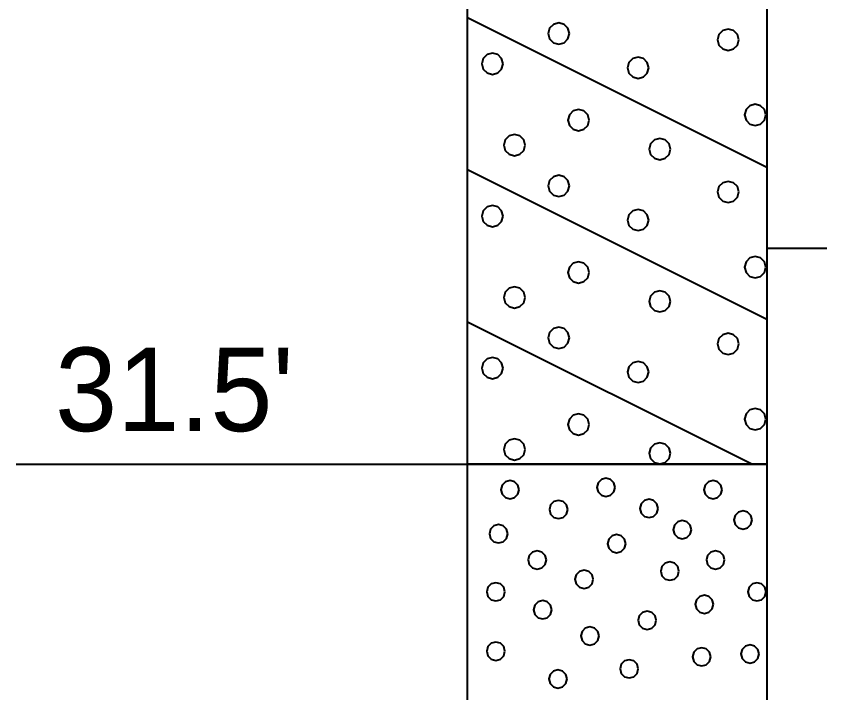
# Model space of a CAD drawing. Extents: x -582 to 653, y -817 to -3.
# Drawn here: x -545.44 to -538.67, y -213.72 to -208.07 of the extents above; entities that cross this region are included whole.
import ezdxf

# ---------------------------------------------------------------- set-up
doc = ezdxf.new("R2010")
doc.units = 0
doc.header["$LTSCALE"] = 0.4
doc.layers.add('27', color=7, linetype='Continuous', lineweight=40)

msp = doc.modelspace()

# ---------------------------------------------------------------- linework, layer by layer
at = {"layer": '27'}
for p, q in [((-541.6718, -208.078), (-539.1718, -209.328)), ((-541.6718, -209.348), (-539.1718, -210.598)), ((-538.6718, -210.008), (-539.1718, -210.008)), ((-541.6718, -210.618), (-539.2918, -211.808)), ((-545.4392, -211.808), (-541.6718, -211.808))]:
    msp.add_line(p, q, dxfattribs=at)
for points in [[(-541.6718, -206.808), (-539.1718, -206.808), (-539.1718, -211.808), (-541.6718, -211.808)], [(-540.8212, -208.2132), (-540.8332, -208.1687), (-540.8657, -208.1362), (-540.9101, -208.1243), (-540.9546, -208.1362), (-540.9871, -208.1687), (-540.999, -208.2132), (-540.9871, -208.2576), (-540.9546, -208.2902), (-540.9101, -208.3021), (-540.8657, -208.2902), (-540.8332, -208.2576)], [(-539.4063, -208.264), (-539.4182, -208.2196), (-539.4508, -208.187), (-539.4952, -208.1751), (-539.5397, -208.187), (-539.5722, -208.2196), (-539.5841, -208.264), (-539.5722, -208.3085), (-539.5397, -208.341), (-539.4952, -208.3529), (-539.4508, -208.341), (-539.4182, -208.3085)], [(-541.3742, -208.4649), (-541.3862, -208.4204), (-541.4187, -208.3879), (-541.4631, -208.376), (-541.5076, -208.3879), (-541.5401, -208.4204), (-541.552, -208.4649), (-541.5401, -208.5093), (-541.5076, -208.5419), (-541.4631, -208.5538), (-541.4187, -208.5419), (-541.3862, -208.5093)], [(-540.1589, -208.4979), (-540.1708, -208.4535), (-540.2034, -208.421), (-540.2478, -208.409), (-540.2923, -208.421), (-540.3248, -208.4535), (-540.3367, -208.4979), (-540.3248, -208.5424), (-540.2923, -208.5749), (-540.2478, -208.5868), (-540.2034, -208.5749), (-540.1708, -208.5424)], [(-539.18, -208.892), (-539.1919, -208.8476), (-539.2245, -208.815), (-539.2689, -208.8031), (-539.3134, -208.815), (-539.3459, -208.8476), (-539.3578, -208.892), (-539.3459, -208.9365), (-539.3134, -208.969), (-539.2689, -208.9809), (-539.2245, -208.969), (-539.1919, -208.9365)], [(-540.6547, -208.9353), (-540.6666, -208.8908), (-540.6992, -208.8583), (-540.7436, -208.8464), (-540.7881, -208.8583), (-540.8206, -208.8908), (-540.8325, -208.9353), (-540.8206, -208.9797), (-540.7881, -209.0122), (-540.7436, -209.0242), (-540.6992, -209.0122), (-540.6666, -208.9797)], [(-541.1899, -209.1437), (-541.2018, -209.0993), (-541.2344, -209.0668), (-541.2788, -209.0548), (-541.3233, -209.0668), (-541.3558, -209.0993), (-541.3677, -209.1437), (-541.3558, -209.1882), (-541.3233, -209.2207), (-541.2788, -209.2326), (-541.2344, -209.2207), (-541.2018, -209.1882)], [(-539.9771, -209.1768), (-539.989, -209.1324), (-540.0216, -209.0998), (-540.066, -209.0879), (-540.1105, -209.0998), (-540.143, -209.1324), (-540.1549, -209.1768), (-540.143, -209.2213), (-540.1105, -209.2538), (-540.066, -209.2657), (-540.0216, -209.2538), (-539.989, -209.2213)], [(-540.8212, -209.4844), (-540.8331, -209.4399), (-540.8656, -209.4074), (-540.9101, -209.3955), (-540.9545, -209.4074), (-540.9871, -209.4399), (-540.999, -209.4844), (-540.9871, -209.5288), (-540.9545, -209.5614), (-540.9101, -209.5733), (-540.8656, -209.5614), (-540.8331, -209.5288)], [(-539.4063, -209.5353), (-539.4182, -209.4908), (-539.4508, -209.4583), (-539.4952, -209.4464), (-539.5397, -209.4583), (-539.5722, -209.4908), (-539.5841, -209.5353), (-539.5722, -209.5797), (-539.5397, -209.6123), (-539.4952, -209.6242), (-539.4508, -209.6123), (-539.4182, -209.5797)], [(-541.3742, -209.7362), (-541.3862, -209.6917), (-541.4187, -209.6592), (-541.4631, -209.6473), (-541.5076, -209.6592), (-541.5401, -209.6917), (-541.552, -209.7362), (-541.5401, -209.7806), (-541.5076, -209.8132), (-541.4631, -209.8251), (-541.4187, -209.8132), (-541.3862, -209.7806)], [(-540.1589, -209.7692), (-540.1708, -209.7248), (-540.2034, -209.6922), (-540.2478, -209.6803), (-540.2923, -209.6922), (-540.3248, -209.7248), (-540.3367, -209.7692), (-540.3248, -209.8137), (-540.2923, -209.8462), (-540.2478, -209.8581), (-540.2034, -209.8462), (-540.1708, -209.8137)], [(-540.6547, -210.2065), (-540.6666, -210.1621), (-540.6992, -210.1295), (-540.7436, -210.1176), (-540.7881, -210.1295), (-540.8206, -210.1621), (-540.8325, -210.2065), (-540.8206, -210.251), (-540.7881, -210.2835), (-540.7436, -210.2954), (-540.6992, -210.2835), (-540.6666, -210.251)], [(-539.18, -210.1633), (-539.1919, -210.1189), (-539.2245, -210.0863), (-539.2689, -210.0744), (-539.3134, -210.0863), (-539.3459, -210.1189), (-539.3578, -210.1633), (-539.3459, -210.2078), (-539.3134, -210.2403), (-539.2689, -210.2522), (-539.2245, -210.2403), (-539.1919, -210.2078)], [(-541.1899, -210.415), (-541.2018, -210.3706), (-541.2344, -210.338), (-541.2788, -210.3261), (-541.3233, -210.338), (-541.3558, -210.3706), (-541.3677, -210.415), (-541.3558, -210.4595), (-541.3233, -210.492), (-541.2788, -210.5039), (-541.2344, -210.492), (-541.2018, -210.4595)], [(-539.9771, -210.4481), (-539.989, -210.4036), (-540.0216, -210.3711), (-540.066, -210.3592), (-540.1105, -210.3711), (-540.143, -210.4036), (-540.1549, -210.4481), (-540.143, -210.4925), (-540.1105, -210.5251), (-540.066, -210.537), (-540.0216, -210.5251), (-539.989, -210.4925)], [(-540.8212, -210.7532), (-540.8332, -210.7087), (-540.8657, -210.6762), (-540.9101, -210.6643), (-540.9546, -210.6762), (-540.9871, -210.7087), (-540.999, -210.7532), (-540.9871, -210.7976), (-540.9546, -210.8302), (-540.9101, -210.8421), (-540.8657, -210.8302), (-540.8332, -210.7976)], [(-539.4063, -210.804), (-539.4182, -210.7596), (-539.4508, -210.727), (-539.4952, -210.7151), (-539.5397, -210.727), (-539.5722, -210.7596), (-539.5841, -210.804), (-539.5722, -210.8485), (-539.5397, -210.881), (-539.4952, -210.8929), (-539.4508, -210.881), (-539.4182, -210.8485)], [(-541.3742, -211.0049), (-541.3862, -210.9604), (-541.4187, -210.9279), (-541.4631, -210.916), (-541.5076, -210.9279), (-541.5401, -210.9604), (-541.552, -211.0049), (-541.5401, -211.0493), (-541.5076, -211.0819), (-541.4631, -211.0938), (-541.4187, -211.0819), (-541.3862, -211.0493)], [(-540.1589, -211.0379), (-540.1708, -210.9935), (-540.2034, -210.961), (-540.2478, -210.949), (-540.2923, -210.961), (-540.3248, -210.9935), (-540.3367, -211.0379), (-540.3248, -211.0824), (-540.2923, -211.1149), (-540.2478, -211.1268), (-540.2034, -211.1149), (-540.1708, -211.0824)], [(-539.18, -211.432), (-539.1919, -211.3876), (-539.2245, -211.355), (-539.2689, -211.3431), (-539.3134, -211.355), (-539.3459, -211.3876), (-539.3578, -211.432), (-539.3459, -211.4765), (-539.3134, -211.509), (-539.2689, -211.5209), (-539.2245, -211.509), (-539.1919, -211.4765)], [(-540.6547, -211.4753), (-540.6666, -211.4308), (-540.6992, -211.3983), (-540.7436, -211.3864), (-540.7881, -211.3983), (-540.8206, -211.4308), (-540.8325, -211.4753), (-540.8206, -211.5197), (-540.7881, -211.5522), (-540.7436, -211.5642), (-540.6992, -211.5522), (-540.6666, -211.5197)], [(-541.1899, -211.6837), (-541.2018, -211.6393), (-541.2344, -211.6068), (-541.2788, -211.5948), (-541.3233, -211.6068), (-541.3558, -211.6393), (-541.3677, -211.6837), (-541.3558, -211.7282), (-541.3233, -211.7607), (-541.2788, -211.7726), (-541.2344, -211.7607), (-541.2018, -211.7282)], [(-539.9771, -211.7168), (-539.989, -211.6724), (-540.0216, -211.6398), (-540.066, -211.6279), (-540.1105, -211.6398), (-540.143, -211.6724), (-540.1549, -211.7168), (-540.143, -211.7613), (-540.1105, -211.7938), (-540.066, -211.8057), (-540.0216, -211.7938), (-539.989, -211.7613)], [(-541.6718, -211.808), (-539.1718, -211.808), (-539.1718, -216.308), (-541.6718, -216.308)], [(-541.2399, -212.0207), (-541.2502, -211.9826), (-541.278, -211.9547), (-541.3161, -211.9445), (-541.3542, -211.9547), (-541.3821, -211.9826), (-541.3923, -212.0207), (-541.3821, -212.0588), (-541.3542, -212.0867), (-541.3161, -212.0969), (-541.278, -212.0867), (-541.2502, -212.0588)], [(-540.439, -212.0011), (-540.4492, -211.963), (-540.4771, -211.9351), (-540.5152, -211.9249), (-540.5533, -211.9351), (-540.5812, -211.963), (-540.5914, -212.0011), (-540.5812, -212.0392), (-540.5533, -212.0671), (-540.5152, -212.0773), (-540.4771, -212.0671), (-540.4492, -212.0392)], [(-539.5453, -212.0207), (-539.5555, -211.9826), (-539.5834, -211.9548), (-539.6215, -211.9445), (-539.6596, -211.9548), (-539.6875, -211.9826), (-539.6977, -212.0207), (-539.6875, -212.0588), (-539.6596, -212.0867), (-539.6215, -212.0969), (-539.5834, -212.0867), (-539.5555, -212.0588)], [(-540.835, -212.186), (-540.8452, -212.1479), (-540.8731, -212.12), (-540.9112, -212.1098), (-540.9493, -212.12), (-540.9772, -212.1479), (-540.9874, -212.186), (-540.9772, -212.2241), (-540.9493, -212.2519), (-540.9112, -212.2622), (-540.8731, -212.2519), (-540.8452, -212.2241)], [(-540.0799, -212.177), (-540.0901, -212.1389), (-540.118, -212.111), (-540.1561, -212.1008), (-540.1942, -212.111), (-540.2221, -212.1389), (-540.2323, -212.177), (-540.2221, -212.2151), (-540.1942, -212.243), (-540.1561, -212.2532), (-540.118, -212.243), (-540.0901, -212.2151)], [(-539.2945, -212.2728), (-539.3047, -212.2347), (-539.3326, -212.2069), (-539.3707, -212.1966), (-539.4088, -212.2069), (-539.4366, -212.2347), (-539.4469, -212.2728), (-539.4366, -212.3109), (-539.4088, -212.3388), (-539.3707, -212.349), (-539.3326, -212.3388), (-539.3047, -212.3109)], [(-539.8017, -212.3542), (-539.8119, -212.3161), (-539.8398, -212.2882), (-539.8779, -212.278), (-539.916, -212.2882), (-539.9439, -212.3161), (-539.9541, -212.3542), (-539.9439, -212.3923), (-539.916, -212.4202), (-539.8779, -212.4304), (-539.8398, -212.4202), (-539.8119, -212.3923)], [(-541.3361, -212.3885), (-541.3463, -212.3504), (-541.3742, -212.3225), (-541.4123, -212.3123), (-541.4504, -212.3225), (-541.4783, -212.3504), (-541.4885, -212.3885), (-541.4783, -212.4266), (-541.4504, -212.4545), (-541.4123, -212.4647), (-541.3742, -212.4545), (-541.3463, -212.4266)], [(-540.35, -212.4717), (-540.3602, -212.4336), (-540.3881, -212.4057), (-540.4262, -212.3955), (-540.4643, -212.4057), (-540.4922, -212.4336), (-540.5024, -212.4717), (-540.4922, -212.5098), (-540.4643, -212.5377), (-540.4262, -212.5479), (-540.3881, -212.5377), (-540.3602, -212.5098)], [(-541.0132, -212.6072), (-541.0234, -212.5691), (-541.0513, -212.5412), (-541.0894, -212.531), (-541.1275, -212.5412), (-541.1554, -212.5691), (-541.1656, -212.6072), (-541.1554, -212.6453), (-541.1275, -212.6732), (-541.0894, -212.6834), (-541.0513, -212.6732), (-541.0234, -212.6453)], [(-539.5246, -212.6072), (-539.5348, -212.5691), (-539.5627, -212.5412), (-539.6008, -212.531), (-539.6389, -212.5412), (-539.6667, -212.5691), (-539.677, -212.6072), (-539.6667, -212.6453), (-539.6389, -212.6732), (-539.6008, -212.6834), (-539.5627, -212.6732), (-539.5348, -212.6453)], [(-539.9059, -212.7), (-539.9161, -212.6619), (-539.944, -212.634), (-539.9821, -212.6238), (-540.0202, -212.634), (-540.0481, -212.6619), (-540.0583, -212.7), (-540.0481, -212.7381), (-540.0202, -212.766), (-539.9821, -212.7762), (-539.944, -212.766), (-539.9161, -212.7381)], [(-540.6217, -212.7686), (-540.6319, -212.7305), (-540.6598, -212.7027), (-540.6979, -212.6924), (-540.736, -212.7027), (-540.7638, -212.7305), (-540.7741, -212.7686), (-540.7638, -212.8067), (-540.736, -212.8346), (-540.6979, -212.8448), (-540.6598, -212.8346), (-540.6319, -212.8067)], [(-541.359, -212.8729), (-541.3692, -212.8348), (-541.3971, -212.8069), (-541.4352, -212.7967), (-541.4733, -212.8069), (-541.5012, -212.8348), (-541.5114, -212.8729), (-541.5012, -212.911), (-541.4733, -212.9389), (-541.4352, -212.9491), (-541.3971, -212.9389), (-541.3692, -212.911)], [(-539.1788, -212.8729), (-539.189, -212.8348), (-539.2169, -212.8069), (-539.255, -212.7967), (-539.2931, -212.8069), (-539.321, -212.8348), (-539.3312, -212.8729), (-539.321, -212.911), (-539.2931, -212.9389), (-539.255, -212.9491), (-539.2169, -212.9389), (-539.189, -212.911)], [(-539.6174, -212.9771), (-539.6276, -212.939), (-539.6555, -212.9111), (-539.6936, -212.9009), (-539.7317, -212.9111), (-539.7595, -212.939), (-539.7698, -212.9771), (-539.7595, -213.0152), (-539.7317, -213.0431), (-539.6936, -213.0533), (-539.6555, -213.0431), (-539.6276, -213.0152)], [(-540.9674, -213.0229), (-540.9777, -212.9848), (-541.0055, -212.9569), (-541.0436, -212.9467), (-541.0817, -212.9569), (-541.1096, -212.9848), (-541.1198, -213.0229), (-541.1096, -213.061), (-541.0817, -213.0889), (-541.0436, -213.0991), (-541.0055, -213.0889), (-540.9777, -213.061)], [(-540.0954, -213.1106), (-540.1056, -213.0725), (-540.1335, -213.0446), (-540.1716, -213.0344), (-540.2097, -213.0446), (-540.2375, -213.0725), (-540.2478, -213.1106), (-540.2375, -213.1487), (-540.2097, -213.1766), (-540.1716, -213.1868), (-540.1335, -213.1766), (-540.1056, -213.1487)], [(-540.5734, -213.2416), (-540.5836, -213.2035), (-540.6115, -213.1756), (-540.6496, -213.1654), (-540.6877, -213.1756), (-540.7155, -213.2035), (-540.7258, -213.2416), (-540.7155, -213.2797), (-540.6877, -213.3075), (-540.6496, -213.3178), (-540.6115, -213.3075), (-540.5836, -213.2797)], [(-541.359, -213.3687), (-541.3692, -213.3306), (-541.3971, -213.3027), (-541.4352, -213.2925), (-541.4733, -213.3027), (-541.5012, -213.3306), (-541.5114, -213.3687), (-541.5012, -213.4068), (-541.4733, -213.4347), (-541.4352, -213.4449), (-541.3971, -213.4347), (-541.3692, -213.4068)], [(-539.6402, -213.4157), (-539.6504, -213.3776), (-539.6783, -213.3497), (-539.7164, -213.3395), (-539.7545, -213.3497), (-539.7824, -213.3776), (-539.7926, -213.4157), (-539.7824, -213.4538), (-539.7545, -213.4817), (-539.7164, -213.4919), (-539.6783, -213.4817), (-539.6504, -213.4538)], [(-539.236, -213.3916), (-539.2462, -213.3535), (-539.2741, -213.3256), (-539.3122, -213.3154), (-539.3503, -213.3256), (-539.3782, -213.3535), (-539.3884, -213.3916), (-539.3782, -213.4297), (-539.3503, -213.4576), (-539.3122, -213.4678), (-539.2741, -213.4576), (-539.2462, -213.4297)], [(-540.2454, -213.5161), (-540.2556, -213.478), (-540.2835, -213.4502), (-540.3216, -213.4399), (-540.3597, -213.4502), (-540.3876, -213.478), (-540.3978, -213.5161), (-540.3876, -213.5542), (-540.3597, -213.5821), (-540.3216, -213.5923), (-540.2835, -213.5821), (-540.2556, -213.5542)], [(-540.8403, -213.6001), (-540.8505, -213.562), (-540.8784, -213.5341), (-540.9165, -213.5239), (-540.9546, -213.5341), (-540.9825, -213.562), (-540.9927, -213.6001), (-540.9825, -213.6382), (-540.9546, -213.666), (-540.9165, -213.6763), (-540.8784, -213.666), (-540.8505, -213.6382)]]:
    msp.add_lwpolyline(points, close=True, dxfattribs=at)

# ---------------------------------------------------------------- texts
msp.add_text("31.5'", height=0.6976, dxfattribs=at).set_placement((-545.1152, -211.5316))

doc.saveas('drawing.dxf')
